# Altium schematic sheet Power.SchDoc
size A; SheetNumber: roneV11-Power; SheetTotal: 6
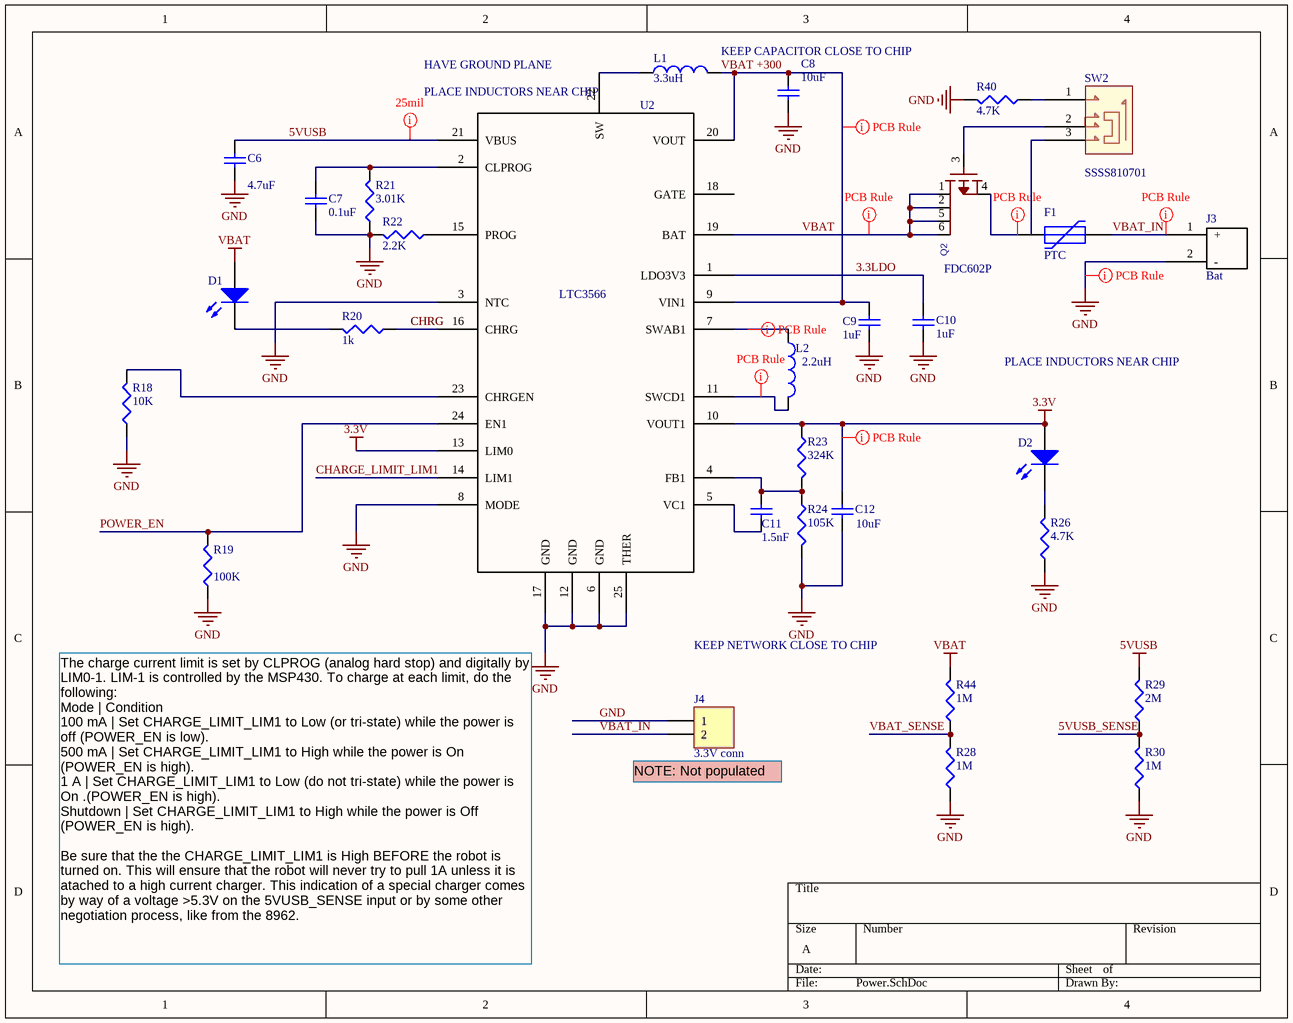
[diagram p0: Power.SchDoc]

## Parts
C6  value 4.7uF  [CAPC1608L]  (hidden comment: Cap Semi)
C7  value 0.1uF  [CAPC1005L]  (hidden comment: Cap)
C8  value 10uF  [CAPC1608L]  (hidden comment: Cap)
C9  value 1uF  [CAPC1608L]  (hidden comment: Cap)
C10  value 1uF  [CAPC1608L]  (hidden comment: Cap)
C11  value 1.5nF  [CAPC1005L]  (hidden comment: Cap)
C12  value 10uF  [CAPC1608L]  (hidden comment: Cap)
D1  Charge  [INDC2012L]  (value not drawn)
D2  Power  [INDC2012L]  (value not drawn)
F1  PTC  [ERJ8G-1206]
J3  Bat  [BatteryConnJST]
J4  3.3V conn  [HDR1X2]
L1  3.3uH  [IndPow]
L2  2.2uH  [IndPow]
Q2  Part Number: FDC602P  [SOT23-6]  (hidden comment: Q_MOSFETP4D_SOT23-6)
R18  value 10K  [RESC1608L]  (hidden comment: Res3)
R19  value 100K  [RESC1608L]  (hidden comment: Res3)
R20  value 1k  [RESC1608L]  (hidden comment: Res3)
R21  value 3.01K  [RESC1608L]  (hidden comment: Res3)
R22  value 2.2K  [RESC1608L]  (hidden comment: Res3)
R23  value 324K  [RESC1608L]  (hidden comment: Res3)
R24  value 105K  [RESC1608L]  (hidden comment: Res3)
R26  value 4.7K  [RESC1608L]  (hidden comment: Res3)
R28  value 1M  [RESC1608L]  (hidden comment: Res3)
R29  value 2M  [RESC1608L]  (hidden comment: Res3)
R30  value 1M  [RESC1608L]  (hidden comment: Res3)
R40  value 4.7K  [RESC1608L]  (hidden comment: Res3)
R44  value 1M  [RESC1608L]  (hidden comment: Res3)
SW2  S_SSSS810701_SSSS810701  [SSSS810701]  (value not drawn)
U2  LTC3566  [QFN-24]

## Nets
3.3V: C12.2 D2.1(A) R23.1 U2.10(VOUT1) U2.13(LIM0)
5VUSB: C6.2 R29.2 U2.21(VBUS)
GND: C6.1 C7.1 C8.1 C9.2 C10.2 C12.1 J3.2(-) J4.1 R18.1 R19.1 R21.1 R22.2 R24.2 R26.1 R28.1 R30.1 R40.2 U2.3(NTC) U2.6(GND) U2.8(MODE) U2.12(GND) U2.17(GND) U2.25(THER)
VBAT: D1.1(A) Q2.1(D) Q2.2(D) Q2.5(D) Q2.6(D) R44.2 U2.19(BAT)
3.3LDO: C10.1 U2.1(LDO3V3)
5VUSB_SENSE: R29.1 R30.2
CHARGE_LIMIT_LIM1: U2.14(LIM1)
CHRG: R20.1 U2.16(CHRG)
POWER_EN: R19.2 U2.24(EN1)
VBAT +300: C8.2 C9.1 L1.2 U2.9(VIN1) U2.20(VOUT)
VBAT_IN: F1.2 J3.1(+) J4.2
VBAT_SENSE: R28.2 R44.1
NetC7_2: C7.2 R21.2 U2.2(CLPROG)
NetC11_1: C11.1 R23.2 R24.1 U2.4(FB1)
NetC11_2: C11.2 U2.5(VC1)
NetD1_2: D1.2(K) R20.2
NetD2_2: D2.2(K) R26.2
NetF1_1: F1.1 Q2.4(S)
NetL1_1: L1.1 U2.22(SW)
NetL2_1: L2.1 U2.7(SWAB1)
NetL2_2: L2.2 U2.11(SWCD1)
NetQ2_3: Q2.3(G) SW2.2
NetR18_2: R18.2 U2.23(CHRGEN)
NetR22_1: R22.1 U2.15(PROG)
NetR40_1: R40.1 SW2.1

Not connected (* = marked no-connect by the designer): SW2 3; U2 18(GATE)

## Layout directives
rule Width Constraint [Pref Width = 25mil    Min Width = 10mil    Max Width = 25mil]: 5VUSB, GND, NetL2_1, NetL2_2, VBAT +300
rule Width Constraint [Pref Width = 25mil    Min Width = 10mil    Max Width = 100mil]: 3.3V
rule Width Constraint [Pref Width = 25mil    Min Width = 10mil    Max Width = 50mil]: NetF1_1, VBAT
rule Width Constraint [Pref Width = 25mil    Min Width = 10mil    Max Width = 40mil]: VBAT_IN

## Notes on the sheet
- (near U2) HAVE GROUND PLANE
- (near U2) PLACE INDUCTORS NEAR CHIP
- KEEP CAPACITOR CLOSE TO CHIP
- CHRG
- PLACE INDUCTORS NEAR CHIP
- KEEP NETWORK CLOSE TO CHIP
- (near J4) NOTE: Not populated
- The charge current limit is set by CLPROG (analog hard stop) and digitally by LIM0-1. LIM-1 is controlled by the MSP430. To charge at each limit, do the following:
  Mode	| Condition
  100 mA	| Set CHARGE_LIMIT_LIM1 to Low (or tri-state) while the power is off (POWER_EN is low).
  500 mA	| Set CHARGE_LIMIT_LIM1 to High while the power is On (POWER_EN is high).
  1 A	| Set CHARGE_LIMIT_LIM1 to Low (do not tri-state) while the power is On .(POWER_EN is high).
  Shutdown | Set CHARGE_LIMIT_LIM1 to High while the power is Off (POWER_EN is high).
  Be sure that the the CHARGE_LIMIT_LIM1 is High BEFORE the robot is turned on. This will ensure that the robot will never try to pull 1A unless it is atached to a high current charger. This indication of a special charger comes by way of a voltage >5.3V on the 5VUSB_SENSE input or by some other negotiation process, like from the 8962.

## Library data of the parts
C6 = Cap Semi: Capacitor (Semiconductor SIM Model); Part Number: JMK107BJ475KA-T; Manufacturer: Taiyo Yuden
C7 = Cap: Capacitor; Part Number: GRM155R71C104KA88D; Manufacturer: Murata
C8 C12 = Cap: Capacitor; Part Number: GRM188R60J106ME47J; Manufacturer: Murata
C9 C10 = Cap: Capacitor; Part Number: LMK107B7105KA-T; Manufacturer: Taiyo Yuden
C11 = Cap: Capacitor; Part Number: GRM155R71H152KA01D; Manufacturer: Murata
D1 = LED2: Typical RED, GREEN, YELLOW, AMBER GaAs LED; Part Number: LTST-C190AKT; Manufacturer: Lite-on
D2 = LED2: Typical RED, GREEN, YELLOW, AMBER GaAs LED; Part Number: LS Q976-nR-1; Manufacturer: Osram
F1 = PTC_FUSE: Fuse; Part Number: MF-NSMF200-2; Manufacturer: Bourns
J3 = BatteryConnJST: Part Number: B2B-PH-K-S(LF)(SN); Manufacturer: JST
J4 = Header 2: Header, 2-Pin
L1 = Inductor: Part Number: LPS 4018-332MLB; Manufacturer: Coilcraft
L2 = Inductor: Part Number: LPS 4018-222MLB; Manufacturer: Coilcraft
Q2 = Q00101: Manufacturer: Fairchild; CPN: Q00101; Rating: -20V -5.5A; Title: Mosfet P-CH -20V -5.5A .035 Ohm SOT23-6; Category Letter: Q
R18 = Res3: Resistor; Part Number: 71-CRCW0603-10K-E3; Manufacturer: Vishay Dale
R19 = Res3: Resistor; Part Number: ERJ-3GEYJ104V; Manufacturer: Panasonic
R20 = Res3: Resistor; Part Number: ERJ-3GEYJ102V; Manufacturer: Panasonic
R21 = Res3: Resistor; Part Number: RMCF0603FT3K01; Manufacturer: Stackpole
R22 = Res3: Resistor; Part Number: ERJ-3GEYJ-222V; Manufacturer: Panasonic
R23 = Res3: Resistor; Part Number: RC0603FR-07324KL; Manufacturer: Yageo
R24 = Res3: Resistor; Part Number: RMCF 1/16 105K 1% R; Manufacturer: Stackpole
R26 R40 = Res3: Resistor; Part Number: ERJ-3GEYJ472V; Manufacturer: Panasonic
R28 R44 = Res3: Resistor; Part Number: ERJ-3GEY-J105V; Manufacturer: Panasonic
R29 R30 = Res3: Resistor; Part Number: ERJ-3GEY-J205V; Manufacturer: Panasonic
SW2 = S_SSSS810701_SSSS810701: SSSS810701; Manufacturer: Alps; FabLevel: SurfaceMount
U2 = LTC3566: Part Number: LTC3566EUF#PBF; Manufacturer: Linear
